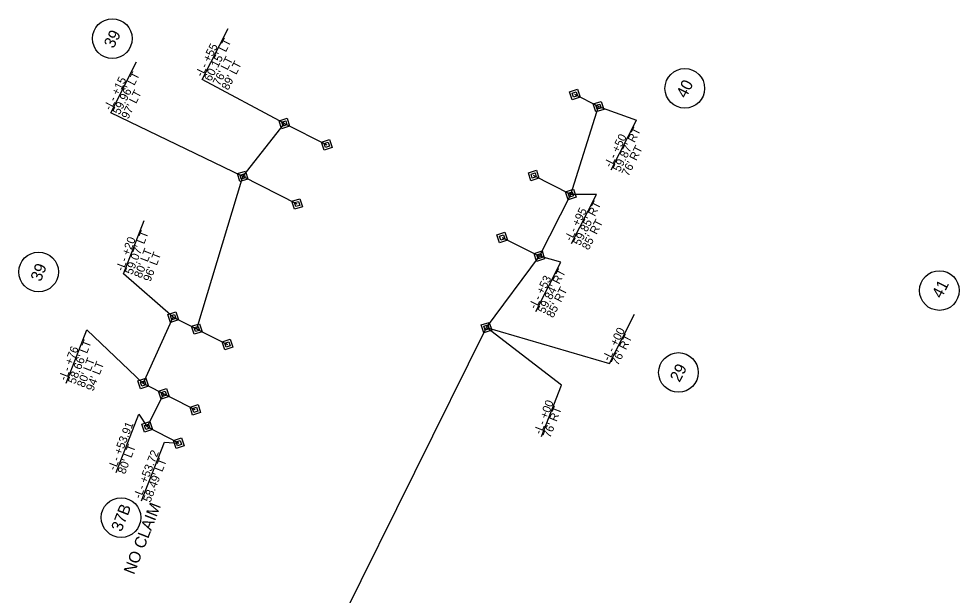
# Model space of a CAD drawing. Extents: x 1975689 to 1978251, y 778490 to 782347.
# Drawn here: x 1977682 to 1978251, y 781998 to 782347 of the extents above; entities that cross this region are included whole.
import ezdxf

# ---------------------------------------------------------------- set-up
doc = ezdxf.new("R2010")
doc.units = 0
for name, color, linetype in [('Prop Easement Aerial Utility', 7, 'Continuous'), ('Prop Easement Aerial Utility Station Offsets', 7, 'Continuous'), ('Prop Easement Permanent Drainage Utility', 7, 'Continuous'), ('Prop Easement Permanent Drainage Utility Station Offsets', 7, 'Continuous'), ('Prop Easement Permanent Utility', 7, 'Continuous'), ('Prop Easement Permanent Utility Station Offsets', 7, 'Continuous'), ('Prop Parcel Number CELL', 7, 'Continuous'), ('Prop ROW Marker CELL', 7, 'Continuous'), ('Prop ROW Permanent Easement CELL', 7, 'Continuous')]:
    doc.layers.add(name, color=color, linetype=linetype)

msp = doc.modelspace()

# ---------------------------------------------------------------- linework, layer by layer
at = {"layer": 'Prop Easement Aerial Utility'}
for p, q in [((1977759.52, 782099.75), (1977769.63, 782119.77)), ((1977778.66, 782089.93), (1977759.52, 782099.75))]:
    msp.add_line(p, q, dxfattribs=at)
at = {"layer": 'Prop Easement Aerial Utility Station Offsets'}
for p, q in [((1977740.77, 782072.17), (1977754.53, 782107.55)), ((1977754.53, 782107.55), (1977759.52, 782099.75)), ((1977756.16, 782055.03), (1977769.92, 782090.41)), ((1977769.92, 782090.41), (1977778.66, 782089.93))]:
    msp.add_line(p, q, dxfattribs=at)
at = {"layer": 'Prop Easement Permanent Drainage Utility'}
for p, q in [((1977817.31, 782251.44), (1977842.53, 782283.5)), ((1977842.53, 782283.5), (1977868.26, 782270.46)), ((1977850.35, 782234.69), (1977817.31, 782251.44)), ((1978015.81, 782240.51), (1977993.38, 782251.88)), ((1977996.83, 782203.05), (1978015.81, 782240.51)), ((1977974.38, 782214.42), (1977996.83, 782203.05)), ((1977757.14, 782126.1), (1977775.25, 782166.25)), ((1977775.25, 782166.25), (1977808.18, 782149.56)), ((1977788.66, 782110.12), (1977757.14, 782126.1))]:
    msp.add_line(p, q, dxfattribs=at)
at = {"layer": 'Prop Easement Permanent Drainage Utility Station Offsets'}
for p, q in [((1977792.84, 782310.07), (1977808.47, 782340.92)), ((1977737.52, 782289.86), (1977753.16, 782320.71)), ((1977842.53, 782283.5), (1977792.84, 782310.07)), ((1977817.31, 782251.44), (1977737.52, 782289.86)), ((1978031.4, 782240.54), (1978015.81, 782240.51)), ((1978016.28, 782210.72), (1978031.4, 782240.54)), ((1977745.12, 782192.51), (1977757.65, 782224.75)), ((1977994.78, 782169.65), (1978009.9, 782199.47)), ((1978009.9, 782199.47), (1977996.83, 782203.05)), ((1977775.25, 782166.25), (1977745.12, 782192.51)), ((1977710.56, 782126.27), (1977723.1, 782158.5)), ((1977723.1, 782158.5), (1977757.14, 782126.1))]:
    msp.add_line(p, q, dxfattribs=at)
at = {"layer": 'Prop Easement Permanent Utility'}
for p, q in [((1978032.65, 782293.64), (1978018.26, 782300.93)), ((1978015.81, 782240.51), (1978032.65, 782293.64)), ((1977789.52, 782159.02), (1977817.31, 782251.44)), ((1977964.84, 782159.84), (1977996.83, 782203.05)), ((1977868.32, 781965.11), (1977964.84, 782159.84))]:
    msp.add_line(p, q, dxfattribs=at)
at = {"layer": 'Prop Easement Permanent Utility Station Offsets'}
for p, q in [((1978032.65, 782293.64), (1978055.55, 782285.38)), ((1978040.33, 782255.39), (1978055.55, 782285.38)), ((1978039.31, 782138.19), (1978054.44, 782168.02)), ((1978010.25, 782125.01), (1977964.84, 782159.84)), ((1977964.84, 782159.84), (1978039.31, 782138.19)), ((1977998.17, 782093.83), (1978010.25, 782125.01))]:
    msp.add_line(p, q, dxfattribs=at)
at = {"layer": 'Prop Parcel Number CELL'}
for p, q in [((1977738.45, 782334.84), (1977738.45, 782334.84)), ((1978084.84, 782304.71), (1978084.84, 782304.71)), ((1977693.86, 782193.55), (1977693.86, 782193.55)), ((1978238.86, 782182.28), (1978238.86, 782182.28)), ((1978080.98, 782132.71), (1978080.98, 782132.71)), ((1977743.71, 782044.82), (1977743.71, 782044.82))]:
    msp.add_line(p, q, dxfattribs=at)
for centre in [(1977738.45, 782334.84), (1978084.84, 782304.71), (1977693.86, 782193.55), (1978238.86, 782182.28), (1978080.98, 782132.71), (1977743.71, 782044.82)]:
    msp.add_circle(centre, 12, dxfattribs=at)
at = {"layer": 'Prop ROW Marker CELL'}
for p, q in [((1978018.26, 782300.93), (1978018.26, 782300.93)), ((1978032.65, 782293.64), (1978032.65, 782293.64)), ((1977842.53, 782283.5), (1977842.53, 782283.5)), ((1977868.26, 782270.46), (1977868.26, 782270.46)), ((1977817.31, 782251.44), (1977817.31, 782251.44)), ((1977993.38, 782251.88), (1977993.38, 782251.88)), ((1978015.81, 782240.51), (1978015.81, 782240.51)), ((1977850.35, 782234.69), (1977850.35, 782234.69)), ((1977974.38, 782214.42), (1977974.38, 782214.42)), ((1977996.82, 782203.05), (1977996.82, 782203.05)), ((1977775.25, 782166.25), (1977775.25, 782166.25)), ((1977789.52, 782159.02), (1977789.52, 782159.02)), ((1977964.83, 782159.84), (1977964.83, 782159.84)), ((1977808.18, 782149.56), (1977808.18, 782149.56)), ((1977757.14, 782126.1), (1977757.14, 782126.1)), ((1977769.63, 782119.77), (1977769.63, 782119.77)), ((1977788.66, 782110.13), (1977788.66, 782110.13)), ((1977759.52, 782099.75), (1977759.52, 782099.75)), ((1977778.66, 782089.93), (1977778.66, 782089.93))]:
    msp.add_line(p, q, dxfattribs=at)
at = {"layer": 'Prop ROW Permanent Easement CELL'}
for points in [[(1978015.05, 782302.56), (1978019.89, 782304.14), (1978021.47, 782299.3), (1978016.64, 782297.72)], [(1978016.66, 782301.74), (1978019.08, 782302.53), (1978019.87, 782300.12), (1978017.45, 782299.32)], [(1978029.44, 782295.26), (1978034.28, 782296.85), (1978035.86, 782292.01), (1978031.03, 782290.42)], [(1978031.05, 782294.45), (1978033.47, 782295.24), (1978034.26, 782292.82), (1978031.84, 782292.03)], [(1977839.32, 782285.13), (1977844.16, 782286.71), (1977845.74, 782281.87), (1977840.9, 782280.29)], [(1977840.92, 782284.31), (1977843.34, 782285.11), (1977844.13, 782282.69), (1977841.72, 782281.89)], [(1977865.05, 782272.09), (1977869.89, 782273.67), (1977871.47, 782268.83), (1977866.63, 782267.25)], [(1977866.65, 782271.27), (1977869.07, 782272.06), (1977869.86, 782269.64), (1977867.44, 782268.85)], [(1977814.1, 782253.07), (1977818.94, 782254.65), (1977820.52, 782249.81), (1977815.68, 782248.23)], [(1977815.7, 782252.25), (1977818.12, 782253.04), (1977818.91, 782250.63), (1977816.49, 782249.83)], [(1977990.17, 782253.51), (1977995.01, 782255.09), (1977996.59, 782250.25), (1977991.75, 782248.67)], [(1977991.78, 782252.69), (1977994.2, 782253.48), (1977994.99, 782251.06), (1977992.57, 782250.27)], [(1978012.6, 782242.14), (1978017.44, 782243.72), (1978019.02, 782238.88), (1978014.19, 782237.3)], [(1978014.21, 782241.32), (1978016.63, 782242.11), (1978017.42, 782239.69), (1978015, 782238.9)], [(1977847.14, 782236.32), (1977851.98, 782237.9), (1977853.56, 782233.06), (1977848.72, 782231.48)], [(1977848.74, 782235.51), (1977851.16, 782236.3), (1977851.95, 782233.88), (1977849.53, 782233.09)], [(1977971.17, 782216.05), (1977976.01, 782217.63), (1977977.59, 782212.79), (1977972.75, 782211.21)], [(1977972.78, 782215.24), (1977975.2, 782216.03), (1977975.99, 782213.61), (1977973.57, 782212.82)], [(1977993.61, 782204.68), (1977998.45, 782206.26), (1978000.04, 782201.42), (1977995.2, 782199.84)], [(1977995.22, 782203.86), (1977997.64, 782204.65), (1977998.43, 782202.23), (1977996.01, 782201.44)], [(1977772.04, 782167.88), (1977776.88, 782169.46), (1977778.46, 782164.62), (1977773.62, 782163.04)], [(1977773.64, 782167.07), (1977776.06, 782167.86), (1977776.85, 782165.44), (1977774.43, 782164.65)], [(1977786.31, 782160.65), (1977791.15, 782162.23), (1977792.73, 782157.39), (1977787.89, 782155.81)], [(1977787.92, 782159.83), (1977790.34, 782160.62), (1977791.13, 782158.2), (1977788.71, 782157.41)], [(1977961.62, 782161.47), (1977966.46, 782163.05), (1977968.04, 782158.21), (1977963.21, 782156.63)], [(1977963.23, 782160.66), (1977965.65, 782161.45), (1977966.44, 782159.03), (1977964.02, 782158.24)], [(1977804.97, 782151.18), (1977809.81, 782152.77), (1977811.39, 782147.93), (1977806.56, 782146.35)], [(1977806.58, 782150.37), (1977809, 782151.16), (1977809.79, 782148.74), (1977807.37, 782147.95)], [(1977753.93, 782127.73), (1977758.77, 782129.31), (1977760.35, 782124.47), (1977755.51, 782122.89)], [(1977755.53, 782126.92), (1977757.95, 782127.71), (1977758.74, 782125.29), (1977756.33, 782124.5)], [(1977766.42, 782121.4), (1977771.26, 782122.98), (1977772.84, 782118.14), (1977768, 782116.56)], [(1977768.02, 782120.59), (1977770.44, 782121.38), (1977771.23, 782118.96), (1977768.81, 782118.17)], [(1977785.45, 782111.75), (1977790.29, 782113.34), (1977791.87, 782108.5), (1977787.03, 782106.91)], [(1977787.05, 782110.94), (1977789.47, 782111.73), (1977790.26, 782109.31), (1977787.84, 782108.52)], [(1977756.31, 782101.37), (1977761.15, 782102.96), (1977762.73, 782098.12), (1977757.89, 782096.53)], [(1977757.91, 782100.56), (1977760.33, 782101.35), (1977761.12, 782098.93), (1977758.71, 782098.14)], [(1977775.45, 782091.56), (1977780.29, 782093.14), (1977781.87, 782088.3), (1977777.03, 782086.72)], [(1977777.05, 782090.74), (1977779.47, 782091.53), (1977780.26, 782089.12), (1977777.84, 782088.32)]]:
    msp.add_lwpolyline(points, close=True, dxfattribs=at)

# ---------------------------------------------------------------- texts
at = {"layer": 'Prop Easement Aerial Utility Station Offsets'}
for s, p in [('-L- +53.91', (1977740.25, 782073.05)), ("80' LT", (1977746.08, 782070.78)), ('-L- +53.72', (1977755.64, 782055.91)), ("58.49' LT", (1977761.46, 782053.64))]:
    msp.add_text(s, height=5, rotation=68.7457, dxfattribs=at).set_placement(p)
at = {"layer": 'Prop Easement Permanent Drainage Utility Station Offsets'}
for s, rotation, p in [("60.15' LT", 63.1199, (1977798.08, 782308.58)), ('-L- +55', 63.1199, (1977792.82, 782311.25)), ("76' LT", 63.1199, (1977803.33, 782305.92)), ("89' LT", 63.1199, (1977808.59, 782303.25)), ("59.96' LT", 63.1199, (1977742.76, 782288.37)), ('-L- +15', 63.1199, (1977737.51, 782291.04)), ("97' LT", 63.1199, (1977748.02, 782285.71)), ('-L- +95', 63.1043, (1978016.13, 782211.77)), ("59.85' RT", 63.1043, (1978021.39, 782209.11)), ("85' RT", 63.1043, (1978026.64, 782206.44)), ("59.07' LT", 68.7457, (1977750.48, 782191.54)), ('-L- +20', 68.7457, (1977744.98, 782193.68)), ("80' LT", 68.7457, (1977755.97, 782189.41)), ("96' LT", 68.7457, (1977761.46, 782187.27)), ("59.84' RT", 63.1043, (1977999.89, 782168.04)), ('-L- +53', 63.1043, (1977994.63, 782170.71)), ("85' RT", 63.1043, (1978005.14, 782165.37)), ('-L- +76', 68.7457, (1977710.43, 782127.44)), ("58.66' LT", 68.7457, (1977715.92, 782125.3)), ("80' LT", 68.7457, (1977721.42, 782123.17)), ("94' LT", 68.7457, (1977726.91, 782121.03))]:
    msp.add_text(s, height=5, rotation=rotation, dxfattribs=at).set_placement(p)
at = {"layer": 'Prop Easement Permanent Utility Station Offsets'}
for s, rotation, p in [("59.87' RT", 63.1043, (1978045.44, 782253.78)), ('-L- +50', 63.1043, (1978040.19, 782256.44)), ("76' RT", 63.1043, (1978050.7, 782251.11)), ('-L- +00', 63.1043, (1978039.16, 782139.25)), ("76' RT", 63.1043, (1978044.42, 782136.58)), ('-L- +00', 68.8203, (1977997.92, 782094.86)), ("76' RT", 68.8203, (1978003.42, 782092.73))]:
    msp.add_text(s, height=5, rotation=rotation, dxfattribs=at).set_placement(p)
at = {"layer": 'Prop Parcel Number CELL'}
for s, rotation, p in [('39', 63.1043, (1977739.14, 782328.47)), ('40', 63.1043, (1978085.5, 782298.29)), ('39', 68.7457, (1977695.16, 782187.29)), ('41', 63.1043, (1978240.15, 782177.09)), ('29', 63.1043, (1978081.67, 782126.34)), ('37B', 68.7457, (1977743.96, 782035.85)), ('NO CLAIM', 68.7457, (1977751.57, 782009.93))]:
    msp.add_text(s, height=7, rotation=rotation, dxfattribs=at).set_placement(p)

doc.saveas('drawing.dxf')
